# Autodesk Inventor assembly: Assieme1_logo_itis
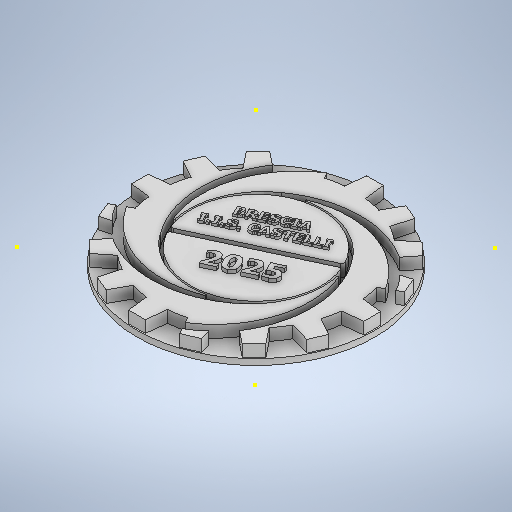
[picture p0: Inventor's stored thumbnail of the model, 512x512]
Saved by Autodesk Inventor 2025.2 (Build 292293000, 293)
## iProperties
Created: 2025-03
Part Number: Assieme1_logo_itis
Document SubType Name: Assembly
Designer: 18907419
Author: 18907419
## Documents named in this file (6)
- C:\test\Assieme1_logo_itis.iam
- C:\test\Parte2_logo_itis.ipt
- C:\test\Parte1_logo_itis.ipt
- C:\test\piatto.ipt
- C:\test\Parte2_logo_itis2.ipt
- C:\test\Parte1_logo_itis copy.ipt
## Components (7 placed, 5 different names)
1. Parte2_logo_itis2:1 — Allineato:1, Angolo:1, Coincidente:2, Allineato:2, Angolo:2, Angolo:3
2. Parte1_logo_itis:2
3. Parte1_logo_itis:3
4. Parte1_logo_itis:4
5. Parte2_logo_itis:2 — Coincidente:2, Allineato:2, Angolo:2, Allineato:3
6. piatto:1 — Allineato:3
7. Parte1_logo_itis copy:1 — Coincidente:1, Allineato:1, Angolo:1
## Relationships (8: Flush 3, Angle 3, Mate 2)
- Coincidente:1 [Mate]: Parte1_logo_itis copy:1
- Allineato:1 [Flush]: Parte2_logo_itis2:1 ↔ Parte1_logo_itis copy:1
- Angolo:1 [Angle]: Parte2_logo_itis2:1 ↔ Parte1_logo_itis copy:1
- Coincidente:2 [Mate]: Parte2_logo_itis2:1 ↔ Parte2_logo_itis:2
- Allineato:2 [Flush]: Parte2_logo_itis2:1 ↔ Parte2_logo_itis:2
- Angolo:2 [Angle]: Parte2_logo_itis2:1 ↔ Parte2_logo_itis:2
- Allineato:3 [Flush]: Parte2_logo_itis:2 ↔ piatto:1
- Angolo:3 [Angle]: Parte2_logo_itis2:1
